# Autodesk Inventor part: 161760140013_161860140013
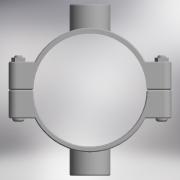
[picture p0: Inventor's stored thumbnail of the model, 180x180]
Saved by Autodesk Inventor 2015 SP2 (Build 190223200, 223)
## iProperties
Created: 2017-05
Part Number: 161760140013_161860140013
Material: Generic
Description: PLASSON DOUBLE SADDLE 140-1.1/4"
Document SubType Name: Modeling
Designer: KIM
Density: 1 g/cm^3
Appearance: Default
Author: KIM
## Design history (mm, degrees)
derived "16176.ipt"
feature "Solid1::16176.ipt"
feature "Solid2::16176.ipt"
tag "TaggingFeature1"
body "Solid1"
body "Solid2"
other parameters: "d0" = 154, "d1" = 201, "d4" = 136, "d5" = 0, "d6" = 10.05, "d7" = 201, "d8" = 0.1, "d10" = 0, "d11" = 1.4, "d20" = 1.4, "d23" = 1.4, "d36" = 15, "d37" = 12, "d38" = 78, "d39" = 0, "d40" = 3, "d41" = 5, "d42" = 0, "d44" = 3, "d45" = 0, "d46" = 1.4, "d52" = 38.952, "d53" = 25, "d54" = 0, "d55" = 32, "d57" = 0, "d58" = 151.2, "d60" = 0, "d62" = 15, "d63" = 12, "d66" = 112, "d67" = 212, "d68" = 50.6376, "d69" = 38.952, "d70" = 25, "d71" = 0, "d72" = 32, "d74" = 0, "d75" = 1.4, "B_" = 32, "G_" = 38.952, "A_" = 106, "L_" = 201, "L_1" = 136, "l_2" = 25
